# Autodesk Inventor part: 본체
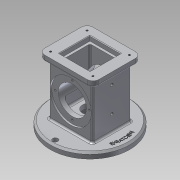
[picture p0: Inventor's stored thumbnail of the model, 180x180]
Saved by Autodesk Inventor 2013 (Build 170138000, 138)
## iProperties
Created: 2019-08
Part Number: 본체
Material: 알루미늄 6061
Document SubType Name: Modeling
Designer: Administrator
Density: 2.71 g/cm^3
Mass: 1042.69 g
Surface Area: 783.574 cm^2
Volume: 384.757 cm^3
Author: Administrator
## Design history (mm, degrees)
node "작업 평면1"
sketch "스케치1"
  geometry: C1 r 67.5 at (0, 0); 1 further point
  constraints: 1 centre point, 1 coincident
  dimensions: "d1" = 135 diameter of C1
extrude "돌출1" new body sketch "스케치1" distance "d2" = 10; taper "d3" = 0 deg
sketch "스케치2"
  geometry: L1 (-37, -33)-(37, -33); L2 (37, -33)-(37, 33); L3 (37, 33)-(-37, 33); L4 (-37, 33)-(-37, -33); L5 (-37, -33)-(37, 33); L6 (37, -33)-(-37, 33); C1 r 67.5 at (0, 0) reference
  constraints: 12 end point, 2 midpoint, 2 parallel, 1 horizontal, 1 perpendicular
  dimensions: "d4" = 74 distance of L2.end L3.end; "d6" = 66 distance of L1.end L2.end
extrude "돌출2" join sketch "스케치2" distance "d7" = 88; taper "d8" = 0 deg
sketch "스케치3"
  geometry: L1 (-46, -41)-(46, -41); L2 (46, -41)-(46, 41); L3 (46, 41)-(-46, 41); L4 (-46, 41)-(-46, -41); L5 (-46, -41)-(46, 41); L6 (46, -41)-(-46, 41); 1 further point
  constraints: 12 end point, 2 midpoint, 2 parallel, 1 horizontal, 1 perpendicular
  dimensions: "d9" = 92 distance of L2.end L3.end; "d11" = 82 distance of L1.end L2.end
extrude "돌출3" join sketch "스케치3" distance "d12" = 10; taper "d13" = 0 deg
sketch "스케치4"
  geometry: C1 r 35 at (37, 44); 1 further point
  constraints: 1 centre point, 1 coincident
  dimensions: "d14" = 70 diameter of C1
extrude "돌출4" cut sketch "스케치4" distance "d15" = 3; taper "d16" = 0 deg
sketch "스케치5"
  geometry: C1 r 35 at (0, 0) reference; C2 r 24 at (0, 0)
  constraints: 1 centre point, 1 coincident
  dimensions: "d17" = 48 diameter of C2
extrude "돌출5" cut sketch "스케치5" stored distance "d18" = 3; taper "d19" = 0 deg
sketch "스케치6"
  geometry: C1 r 24 at (37, -44) reference; C2 r 35 at (37, -44)
  constraints: 1 centre point, 1 coincident
  dimensions: "d20" = 70 diameter of C2
extrude "돌출6" cut sketch "스케치6" distance "d21" = 3; taper "d22" = 0 deg
sketch "스케치7"
  geometry: L1 (-26, -26)-(26, -26); L2 (26, -26)-(26, 26); L3 (26, 26)-(-26, 26); L4 (-26, 26)-(-26, -26); L5 (-26, -26)-(26, 26); L6 (26, -26)-(-26, 26); 1 further point
  constraints: 12 end point, 2 midpoint, 2 parallel, 1 horizontal, 1 perpendicular
  dimensions: "d23" = 52 distance of L2.end L3.end; "d25" = 52 distance of L1.end L2.end
extrude "돌출7" cut sketch "스케치7" distance "d26" = 8; taper "d27" = 0 deg
sketch "스케치8"
  geometry: L1 (-22, -22)-(22, -22); L2 (22, -22)-(22, 22); L3 (22, 22)-(-22, 22); L4 (-22, 22)-(-22, -22); L5 (-22, -22)-(22, 22); L6 (22, -22)-(-22, 22); 1 further point
  constraints: 12 end point, 2 midpoint, 2 parallel, 1 horizontal, 1 perpendicular
  dimensions: "d28" = 44 distance of L2.end L3.end; "d30" = 44 distance of L1.end L2.end
extrude "돌출8" cut sketch "스케치8" distance "d31" = 74; taper "d32" = 0 deg
sketch "스케치9"
  geometry: C1 r 67.5 at (0, 0) reference; C2 r 25 at (0, 0)
  constraints: 1 centre point, 1 coincident
  dimensions: "d33" = 50 diameter of C2
extrude "돌출9" cut sketch "스케치9" distance "d34" = 18; taper "d35" = 0 deg
sketch "스케치10"
  geometry: C1 r 25 at (0, 0) reference; C2 r 12.5 at (0, 0)
  constraints: 1 centre point, 1 coincident
  dimensions: "d36" = 25 diameter of C2
extrude "돌출10" cut sketch "스케치10" distance "d37" = 18; taper "d38" = 0 deg
sketch "스케치11"
  geometry: C1 r 67.5 at (0, 0) reference; C2 r 4.5 at (0, 59); C3 r 4.5 at (-59, 0); C4 r 4.5 at (0, -59); A1 r 59 centre (0, 0) between (0, 59) and (-59, 0)
  constraints: 4 centre point, 3 point on circle, 2 vertical alignment, 1 coincident, 1 horizontal alignment
  dimensions: "d39" = 118 diameter of A1; "d40" = 9 diameter of C2; "d41" = 9 diameter of C3; "d42" = 9 diameter of C4
extrude "돌출11" cut sketch "스케치11" stored distance "d43" = 18; taper "d44" = 0 deg
sketch "스케치12"
  geometry: L1 (10, -34.5)-(10, 100.5) reference; 3 further points
  constraints: 2 horizontal alignment
  dimensions: "d45" = 37 distance from line of point (-27, 33) L1; "d46" = 43 distance of point (-70, 33) point (-27, 33)
hole "구멍1" sketch "스케치12" at (-70, 33), (-27, 33) diameter "d47" = 4.917; stored, may be unused: countersink angle "d51" = 90 deg, drill point angle "d53" = 0 deg; dims "d48" = 6, "d49" = 4, "d50" = 2, "d52" = 28
fillet "모깎기1" dims "d60" = 10
sketch "스케치16"
  geometry: A1 r 10 centre (-36, 31) between (-36, 41) and (-46, 31) reference; A2 r 10 centre (-36, -31) between (-46, -31) and (-36, -41) reference; A3 r 10 centre (36, -31) between (36, -41) and (46, -31) reference; A4 r 10 centre (36, 31) between (46, 31) and (36, 41) reference; 1 further point
hole "구멍2" sketch "스케치16" at (-36, 31), (36, 31), (36, -31), (-36, -31) diameter "d61" = 3.242; stored, may be unused: countersink angle "d65" = 90 deg, drill point angle "d67" = 118 deg; dims "d62" = 4, "d63" = 4, "d64" = 2, "d66" = 6
sketch "스케치17" dims "d68" = 58
  geometry: C1 r 24 at (0, 0) reference; C2 r 35 at (0, 0) reference; 2 further points
  constraints: 2 vertical alignment, 1 coincident, 2 other
hole "구멍3" sketch "스케치17" at (0, 29) diameter "d70" = 3.242; stored, may be unused: countersink angle "d74" = 90 deg, drill point angle "d76" = 118 deg; dims "d71" = 4, "d72" = 4, "d73" = 2, "d75" = 6
node "작업 평면2"
node "작업 평면4"
sketch "스케치18"
  geometry: C1 r 59 at (0, 0); 1 further point
  constraints: 1 centre point, 1 coincident, 1 other
  dimensions: "d82" = 118 diameter of C1
feature "엠보싱1" sketch "스케치18" dims "d1" = 135, "d9" = 92, "d11" = 82, "d83" = 0.5, "d84" = 0
chamfer "모따기1" distance "d85" = 3; stored, may be unused: second distance "d86" = 2, angle "d87" = 45 deg
chamfer "모따기2" distance "d88" = 1; stored, may be unused: second distance "d89" = 2, angle "d90" = 45 deg
fillet "모깎기2" dims "d91" = 3
fillet "모깎기3" dims "d92" = 3
fillet "모깎기4" dims "d93" = 3
fillet "모깎기5" dims "d94" = 3
fillet "모깎기6" dims "d95" = 3
fillet "모깎기7" dims "d96" = 3
node "솔리드1"
pattern_circular "원형 패턴1" dims angle "d78" = 360 deg
mirror "대칭1"
other parameters: "d0" = -54, "d81" = 31
